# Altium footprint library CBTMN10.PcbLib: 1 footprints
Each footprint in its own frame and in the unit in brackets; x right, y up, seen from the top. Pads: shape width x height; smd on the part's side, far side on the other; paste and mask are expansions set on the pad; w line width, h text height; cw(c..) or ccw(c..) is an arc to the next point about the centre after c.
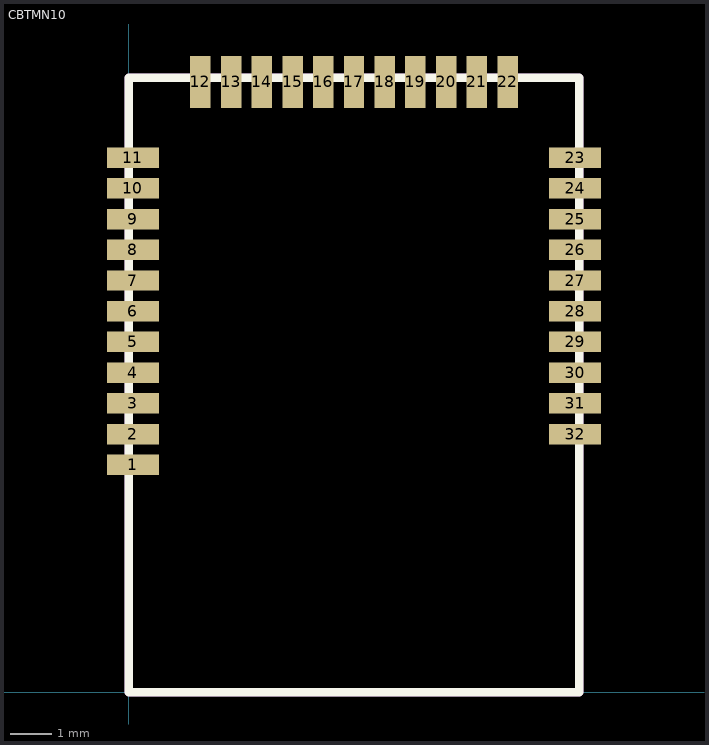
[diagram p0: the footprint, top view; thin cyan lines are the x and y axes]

## CBTMN10 [mm]
pads (32):
  rect 1.27x0.5 smd mask+0.064: 1(0.1,5.55) 2(0.1,6.3) 3(0.1,7.05) 4(0.1,7.8) 5(0.1,8.55) 6(0.1,9.3) 7(0.1,10.05) 8(0.1,10.8) 9(0.1,11.55) 10(0.1,12.3) 11(0.1,13.05) 23(10.9,13.05) 24(10.9,12.3) 25(10.9,11.55) 26(10.9,10.8) 27(10.9,10.05) 28(10.9,9.3) 29(10.9,8.55) 30(10.9,7.8) 31(10.9,7.05) 32(10.9,6.3)
  rect 0.5x1.27 smd mask+0.064: 12(1.75,14.9) 13(2.5,14.9) 14(3.25,14.9) 15(4,14.9) 16(4.75,14.9) 17(5.5,14.9) 18(6.25,14.9) 19(7,14.9) 20(7.75,14.9) 21(8.5,14.9) 22(9.25,14.9)
L26-Silk Screen Top (Multiple PADS layers...):
  lines w0.2: 0,0 11,0 11,15 0,15 0,0
L15 (Multiple PADS layers...):
  lines w0.127: 0.016,5.386 ccw(c0.079,5.551) 0.016,5.716 ; 0.016,6.136 ccw(c0.079,6.301) 0.016,6.466 ; 0.016,6.886 ccw(c0.079,7.051) 0.016,7.216 ; 0.016,7.636 ccw(c0.079,7.801) 0.016,7.966 ; 0.016,8.386 ccw(c0.079,8.551) 0.016,8.716 ; 0.016,9.136 ccw(c0.079,9.301) 0.016,9.466 ; 0.016,9.886 ccw(c0.079,10.051) 0.016,10.216 ; 0.016,10.636 ccw(c0.079,10.801) 0.016,10.966 ; 0.016,11.386 ccw(c0.079,11.551) 0.016,11.716 ; 0.016,12.136 ccw(c0.079,12.301) 0.016,12.466 ; 0.016,12.886 ccw(c0.079,13.051) 0.016,13.216 ; 1.589,14.979 ccw(c1.754,14.916) 1.919,14.979 ; 2.339,14.979 ccw(c2.504,14.916) 2.669,14.979 ; 3.089,14.979 ccw(c3.254,14.916) 3.419,14.979 ; 3.839,14.979 ccw(c4.004,14.916) 4.169,14.979 ; 4.589,14.979 ccw(c4.754,14.916) 4.919,14.979 ; 5.339,14.979 ccw(c5.504,14.916) 5.669,14.979 ; 6.089,14.979 ccw(c6.254,14.916) 6.419,14.979 ; 6.839,14.979 ccw(c7.004,14.916) 7.169,14.979 ; 7.589,14.979 ccw(c7.754,14.916) 7.919,14.979 ; 8.339,14.979 ccw(c8.504,14.916) 8.669,14.979 ; 9.089,14.979 ccw(c9.254,14.916) 9.419,14.979 ; 10.953,6.136 cw(c10.89,6.301) 10.953,6.466 ; 10.953,6.886 cw(c10.89,7.051) 10.953,7.216 ; 10.953,7.636 cw(c10.89,7.801) 10.953,7.966 ; 10.953,8.386 cw(c10.89,8.551) 10.953,8.716 ; 10.953,9.136 cw(c10.89,9.301) 10.953,9.466 ; 10.953,9.886 cw(c10.89,10.051) 10.953,10.216 ; 10.953,10.636 cw(c10.89,10.801) 10.953,10.966 ; 10.953,11.386 cw(c10.89,11.551) 10.953,11.716 ; 10.953,12.136 cw(c10.89,12.301) 10.953,12.466 ; 10.953,12.886 cw(c10.89,13.051) 10.953,13.216
  lines w0.2: 0,0 11,0 11,15 0,15 0,0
